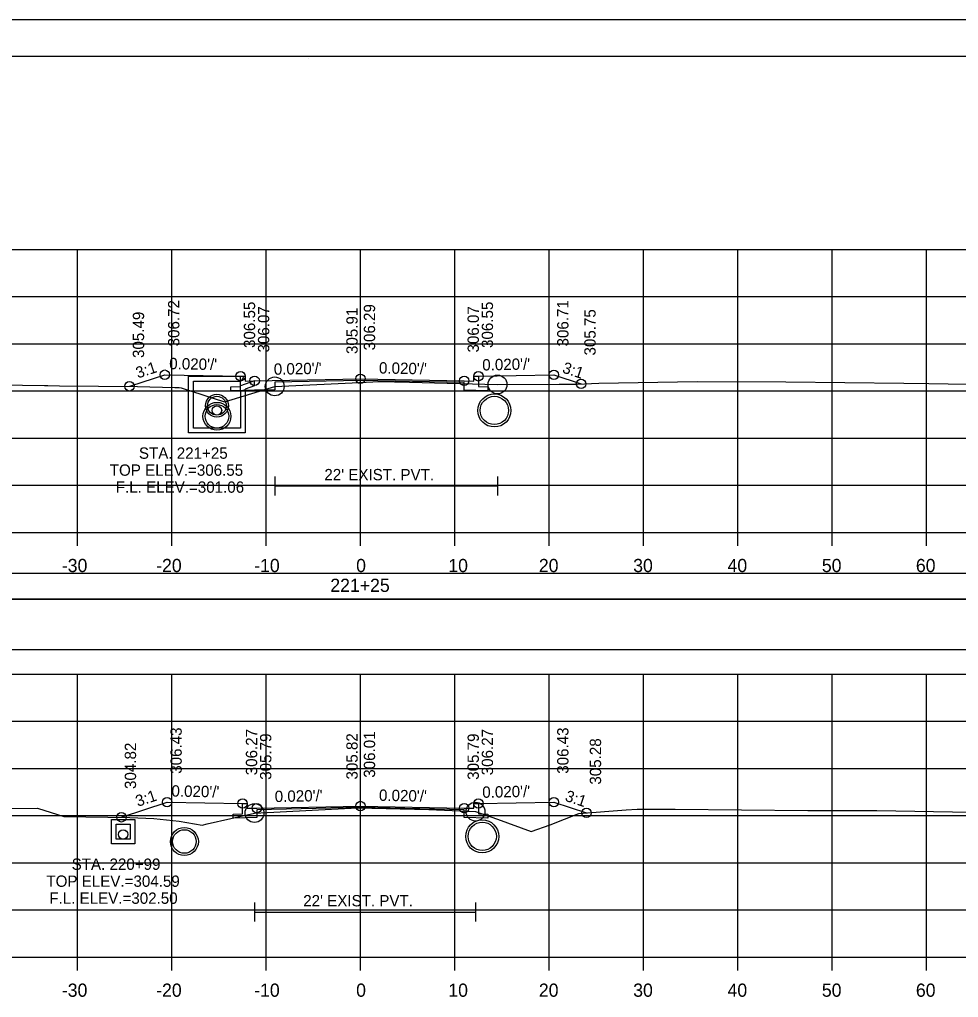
# Model space of a CAD drawing. Extents: x 1370538 to 1372872, y 376220 to 381127.
# Drawn here: x 1372672.5 to 1372772, y 379377.7 to 379481.3 of the extents above; entities that cross this region are included whole.
import ezdxf

# ---------------------------------------------------------------- set-up
doc = ezdxf.new("R2010")
doc.units = 0
for name, color, linetype in [('R_Border', 7, 'Continuous'), ('R_Border Notes', 7, 'Continuous'), ('R_Border PE', 7, 'Continuous'), ('R_Border Prem', 7, 'Continuous'), ('R_Dimension', 7, 'Continuous'), ('R_Fin Surface', 7, 'Continuous'), ('R_Grid', 7, 'Continuous'), ('R_No Plot', 7, 'Continuous'), ('R_Water', 7, 'Continuous'), ('R_Water Annot', 7, 'Continuous'), ('R_Xsect Elev', 7, 'Continuous'), ('R_Xsect Slope', 7, 'Continuous'), ('T_Detection Zones', 7, 'Continuous')]:
    doc.layers.add(name, color=color, linetype=linetype)

msp = doc.modelspace()

# ---------------------------------------------------------------- linework, layer by layer
at = {"layer": 'R_Border'}
for p, q in [((1372699.56, 379432.88), (1372699.56, 379430.88)), ((1372723.18, 379432.88), (1372723.18, 379430.88)), ((1372699.56, 379431.88), (1372723.18, 379431.88)), ((1372697.41, 379387.73), (1372697.41, 379385.73)), ((1372720.84, 379387.73), (1372720.84, 379385.73)), ((1372697.41, 379386.73), (1372720.84, 379386.73))]:
    msp.add_line(p, q, dxfattribs=at)
for points in [[(1372708.65, 379443.07), (1372699.56, 379442.89), (1372699.56, 379442.06), (1372697.43, 379442.02), (1372694.92, 379441.97), (1372694.92, 379442.39), (1372695.93, 379442.41), (1372695.93, 379443.5)], [(1372721.15, 379443.5), (1372721.15, 379442.41), (1372722.15, 379442.39), (1372722.15, 379441.97), (1372719.65, 379442.02), (1372719.65, 379442.02), (1372719.65, 379442.85), (1372708.65, 379443.07)], [(1372708.65, 379397.79), (1372697.65, 379397.57), (1372697.65, 379396.74), (1372697.65, 379396.74), (1372695.15, 379396.69), (1372695.15, 379397.11), (1372696.15, 379397.13), (1372696.15, 379398.22)], [(1372721.15, 379398.22), (1372721.15, 379397.13), (1372722.15, 379397.11), (1372722.15, 379396.69), (1372719.65, 379396.74), (1372719.65, 379396.74), (1372719.65, 379397.57), (1372708.65, 379397.79)]]:
    msp.add_lwpolyline(points, dxfattribs=at)
at = {"layer": 'R_Border Notes'}
for p, q in [((1372550.65, 379477.41), (1372866.83, 379477.41)), ((1372703.17, 379477.15), (1372703.17, 379477.15)), ((1372703.17, 379477.15), (1372703.17, 379477.15))]:
    msp.add_line(p, q, dxfattribs=at)
at = {"layer": 'R_Border Prem'}
for p, q in [((1372558.65, 379426.95), (1372858.65, 379426.95)), ((1372678.65, 379425.55), (1372678.65, 379426.95)), ((1372688.65, 379425.55), (1372688.65, 379426.95)), ((1372698.65, 379425.55), (1372698.65, 379426.95)), ((1372708.65, 379425.55), (1372708.65, 379426.95)), ((1372718.65, 379425.55), (1372718.65, 379426.95)), ((1372728.65, 379425.55), (1372728.65, 379426.95)), ((1372738.65, 379425.55), (1372738.65, 379426.95)), ((1372748.65, 379425.55), (1372748.65, 379426.95)), ((1372758.65, 379425.55), (1372758.65, 379426.95)), ((1372768.65, 379425.55), (1372768.65, 379426.95)), ((1372558.65, 379381.95), (1372858.65, 379381.95)), ((1372678.65, 379380.55), (1372678.65, 379381.95)), ((1372688.65, 379380.55), (1372688.65, 379381.95)), ((1372698.65, 379380.55), (1372698.65, 379381.95)), ((1372708.65, 379380.55), (1372708.65, 379381.95)), ((1372718.65, 379380.55), (1372718.65, 379381.95)), ((1372728.65, 379380.55), (1372728.65, 379381.95)), ((1372738.65, 379380.55), (1372738.65, 379381.95)), ((1372748.65, 379380.55), (1372748.65, 379381.95)), ((1372758.65, 379380.55), (1372758.65, 379381.95)), ((1372768.65, 379380.55), (1372768.65, 379381.95))]:
    msp.add_line(p, q, dxfattribs=at)
at = {"layer": 'R_Dimension'}
for points in [[(1372665.8, 379442.68), (1372675.15, 379442.53), (1372675.33, 379442.52), (1372675.52, 379442.52), (1372676.75, 379442.5), (1372685.01, 379442.43), (1372688.98, 379442.33), (1372689.43, 379442.32), (1372689.63, 379442.26), (1372694.24, 379440.79), (1372699.21, 379442.32), (1372699.56, 379442.43), (1372709.24, 379442.89), (1372710.67, 379442.95), (1372713.86, 379442.87), (1372723.18, 379442.63), (1372729.71, 379442.67), (1372731.63, 379442.68), (1372733.93, 379442.77), (1372744.36, 379442.96), (1372753.74, 379442.93), (1372766.25, 379442.76), (1372768.9, 379442.75), (1372775.04, 379442.64)], [(1372660.62, 379397.55), (1372674.4, 379397.75), (1372677.21, 379396.87), (1372684.21, 379396.75), (1372686.74, 379396.63), (1372689.41, 379396.36), (1372691.88, 379395.94), (1372692.4, 379396.09), (1372697.41, 379397.22), (1372703.53, 379397.54), (1372708.35, 379397.78), (1372715.89, 379397.58), (1372720.84, 379397.37), (1372723.18, 379396.57), (1372726.74, 379395.27), (1372728.75, 379395.98), (1372731.8, 379397.16), (1372736.83, 379397.56), (1372737.98, 379397.63), (1372742.02, 379397.62), (1372756.09, 379397.48), (1372763.38, 379397.5), (1372773.43, 379397.32)]]:
    msp.add_lwpolyline(points, dxfattribs=at)
at = {"layer": 'R_Fin Surface'}
for points in [[(1372684.16, 379442.44), (1372684.3, 379442.48), (1372687.9, 379443.67), (1372694.03, 379443.54), (1372695.93, 379443.5), (1372696.4, 379443.5), (1372696.43, 379443.5), (1372696.43, 379443.03), (1372696.43, 379443), (1372697.43, 379443.02), (1372708.65, 379443.24)], [(1372708.65, 379443.24), (1372719.65, 379443.02), (1372720.65, 379443), (1372720.65, 379443.5), (1372721.15, 379443.5), (1372729.15, 379443.66), (1372732.03, 379442.7)], [(1372683.31, 379396.77), (1372688.15, 379398.38), (1372696.15, 379398.22), (1372696.65, 379398.22), (1372696.65, 379397.72), (1372697.65, 379397.74), (1372708.65, 379397.96)], [(1372708.65, 379397.96), (1372719.65, 379397.74), (1372720.65, 379397.72), (1372720.65, 379398.22), (1372721.15, 379398.22), (1372729.15, 379398.38), (1372732.61, 379397.23)]]:
    msp.add_lwpolyline(points, dxfattribs=at)
at = {"layer": 'R_Grid'}
for p, q in [((1372558.65, 379456.95), (1372858.65, 379456.95)), ((1372678.65, 379426.95), (1372678.65, 379456.95)), ((1372688.65, 379426.95), (1372688.65, 379456.95)), ((1372698.65, 379426.95), (1372698.65, 379456.95)), ((1372708.65, 379426.95), (1372708.65, 379456.95)), ((1372718.65, 379426.95), (1372718.65, 379456.95)), ((1372728.65, 379426.95), (1372728.65, 379456.95)), ((1372738.65, 379426.95), (1372738.65, 379456.95)), ((1372748.65, 379426.95), (1372748.65, 379456.95)), ((1372758.65, 379426.95), (1372758.65, 379456.95)), ((1372768.65, 379426.95), (1372768.65, 379456.95)), ((1372558.65, 379451.95), (1372858.65, 379451.95)), ((1372558.65, 379446.95), (1372858.65, 379446.95)), ((1372558.65, 379441.95), (1372858.65, 379441.95)), ((1372558.65, 379436.95), (1372858.65, 379436.95)), ((1372558.65, 379431.95), (1372858.65, 379431.95)), ((1372558.65, 379426.95), (1372858.65, 379426.95)), ((1372558.65, 379411.95), (1372858.65, 379411.95)), ((1372678.65, 379381.95), (1372678.65, 379411.95)), ((1372688.65, 379381.95), (1372688.65, 379411.95)), ((1372698.65, 379381.95), (1372698.65, 379411.95)), ((1372708.65, 379381.95), (1372708.65, 379411.95)), ((1372718.65, 379381.95), (1372718.65, 379411.95)), ((1372728.65, 379381.95), (1372728.65, 379411.95)), ((1372738.65, 379381.95), (1372738.65, 379411.95)), ((1372748.65, 379381.95), (1372748.65, 379411.95)), ((1372758.65, 379381.95), (1372758.65, 379411.95)), ((1372768.65, 379381.95), (1372768.65, 379411.95)), ((1372558.65, 379406.95), (1372858.65, 379406.95)), ((1372558.65, 379401.95), (1372858.65, 379401.95)), ((1372558.65, 379396.95), (1372858.65, 379396.95)), ((1372558.65, 379391.95), (1372858.65, 379391.95)), ((1372558.65, 379386.95), (1372858.65, 379386.95)), ((1372558.65, 379381.95), (1372858.65, 379381.95))]:
    msp.add_line(p, q, dxfattribs=at)
at = {"layer": 'R_No Plot'}
msp.add_line((1372538.25, 379481.3), (1372871.58, 379481.3), dxfattribs=at)
for points in [[(1372538.24, 379481.3), (1372871.58, 379481.3), (1372871.58, 379267.96), (1372538.24, 379267.96)], [(1372784.57, 379477.41), (1372784.57, 379467.53), (1372820.3, 379467.53), (1372820.3, 379464.61), (1372843.5, 379464.61), (1372843.5, 379440.27), (1372866.83, 379440.27), (1372866.83, 379271.95), (1372550.65, 379271.95), (1372550.65, 379477.41)]]:
    msp.add_lwpolyline(points, close=True, dxfattribs=at)
for centre, radius in [((1372687.9, 379443.67), 0.5), ((1372695.93, 379443.5), 0.5), ((1372721.15, 379443.5), 0.5), ((1372729.15, 379443.66), 0.5), ((1372684.16, 379442.44), 0.5), ((1372697.43, 379443.02), 0.5), ((1372699.56, 379442.43), 1), ((1372708.65, 379443.24), 0.5), ((1372708.65, 379443.24), 0.5), ((1372719.65, 379443.02), 0.5), ((1372723.18, 379442.63), 1), ((1372732.03, 379442.7), 0.5), ((1372693.43, 379439.26), 1.48), ((1372693.43, 379440.38), 1.21), ((1372722.84, 379439.88), 1.75), ((1372693.43, 379439.88), 0.505), ((1372688.15, 379398.38), 0.5), ((1372696.15, 379398.22), 0.5), ((1372697.41, 379397.22), 1), ((1372697.65, 379397.74), 0.5), ((1372708.65, 379397.96), 0.5), ((1372708.65, 379397.96), 0.5), ((1372719.65, 379397.74), 0.5), ((1372720.84, 379397.37), 1), ((1372721.15, 379398.22), 0.5), ((1372729.15, 379398.38), 0.5), ((1372683.31, 379396.77), 0.5), ((1372732.61, 379397.23), 0.5), ((1372721.56, 379394.75), 1.75), ((1372683.49, 379394.95), 0.505), ((1372689.98, 379394.2), 1.48)]:
    msp.add_circle(centre, radius, dxfattribs=at)
at = {"layer": 'R_Water'}
for p, q in [((1372690.43, 379443.5), (1372696.18, 379443.5)), ((1372690.43, 379442), (1372690.43, 379443.5)), ((1372690.93, 379442), (1372690.93, 379443)), ((1372690.93, 379443), (1372695.93, 379443)), ((1372696.26, 379443.34), (1372695.93, 379443)), ((1372697.43, 379443.02), (1372695.93, 379442.5)), ((1372696.26, 379443.34), (1372696.18, 379443.5)), ((1372695.93, 379442), (1372695.93, 379442.5)), ((1372697.43, 379442.49), (1372696.43, 379442.15)), ((1372696.43, 379442), (1372696.43, 379442.15))]:
    msp.add_line(p, q, dxfattribs=at)
for points in [[(1372697.43, 379442.49), (1372697.43, 379443.02)], [(1372696.43, 379442), (1372696.43, 379437.51), (1372693.43, 379437.51), (1372690.43, 379437.51), (1372690.43, 379442)], [(1372695.93, 379442), (1372695.93, 379438.01), (1372693.43, 379438.01), (1372690.93, 379438.01), (1372690.93, 379442)]]:
    msp.add_lwpolyline(points, dxfattribs=at)
for points in [[(1372551.05, 379414.56), (1372866.18, 379414.56), (1372866.18, 379419.88), (1372551.05, 379419.88)], [(1372683.49, 379396.53), (1372684.74, 379396.53), (1372684.74, 379393.95), (1372683.49, 379393.95), (1372682.24, 379393.95), (1372682.24, 379396.53)], [(1372683.49, 379396.03), (1372684.24, 379396.03), (1372684.24, 379394.45), (1372683.49, 379394.45), (1372682.74, 379394.45), (1372682.74, 379396.03)]]:
    msp.add_lwpolyline(points, close=True, dxfattribs=at)
for centre, radius in [((1372693.43, 379440.38), 1), ((1372722.84, 379439.88), 1.5), ((1372693.43, 379439.26), 1.25), ((1372693.43, 379439.88), 0.5), ((1372721.56, 379394.75), 1.5), ((1372683.49, 379394.95), 0.5), ((1372689.98, 379394.2), 1.25)]:
    msp.add_circle(centre, radius, dxfattribs=at)
at = {"layer": 'R_Xsect Elev'}
for p, q in [((1372708.65, 379442.86), (1372708.65, 379452.86)), ((1372708.65, 379397.77), (1372708.65, 379407.77))]:
    msp.add_line(p, q, dxfattribs=at)
at = {"layer": 'T_Detection Zones'}
msp.add_lwpolyline([(1372551.05, 379419.88), (1372866.18, 379419.88), (1372866.18, 379422.59), (1372551.05, 379422.59)], close=True, dxfattribs=at)

# ---------------------------------------------------------------- texts
at = {"layer": 'R_Border PE'}
for s, p in [('-30', (1372676.99, 379422.75)), ('-20', (1372686.99, 379422.75)), ('-10', (1372697.38, 379422.75)), ('0', (1372708.19, 379422.75)), ('10', (1372717.96, 379422.75)), ('20', (1372727.56, 379422.75)), ('30', (1372737.56, 379422.75)), ('40', (1372747.56, 379422.75)), ('50', (1372757.56, 379422.75)), ('60', (1372767.53, 379422.75)), ('221+25', (1372705.45, 379420.65)), ('-30', (1372676.99, 379377.75)), ('-20', (1372686.99, 379377.75)), ('-10', (1372697.38, 379377.75)), ('0', (1372708.19, 379377.75)), ('10', (1372717.96, 379377.75)), ('20', (1372727.56, 379377.75)), ('30', (1372737.56, 379377.75)), ('40', (1372747.56, 379377.75)), ('50', (1372757.56, 379377.75)), ('60', (1372767.53, 379377.75))]:
    msp.add_text(s, height=1.4, dxfattribs=at).set_placement(p)
at = {"layer": 'R_Water'}
for p in [(1372704.82, 379432.48), (1372702.58, 379387.33)]:
    msp.add_text("22' EXIST. PVT.", height=1.2, dxfattribs=at).set_placement(p)
at = {"layer": 'R_Water Annot'}
for s, p in [('STA. 221+25', (1372685.16, 379434.76)), ('TOP ELEV.=306.55', (1372682.07, 379432.96)), ('F.L. ELEV.=301.06', (1372682.71, 379431.16)), ('STA. 220+99', (1372678.03, 379391.2)), ('TOP ELEV.=304.59', (1372675.35, 379389.4)), ('F.L. ELEV.=302.50', (1372675.66, 379387.6))]:
    msp.add_text(s, height=1.2, dxfattribs=at).set_placement(p)
at = {"layer": 'R_Xsect Elev'}
for s, p in [('306.72', (1372689.45, 379446.67)), ('306.55', (1372697.48, 379446.5)), ('306.29', (1372710.2, 379446.24)), ('306.29', (1372710.2, 379446.24)), ('306.55', (1372722.7, 379446.5)), ('306.71', (1372730.7, 379446.66)), ('305.49', (1372685.71, 379445.44)), ('306.07', (1372698.98, 379446.02)), ('305.91', (1372708.35, 379445.86)), ('306.07', (1372721.2, 379446.02)), ('305.75', (1372733.58, 379445.7)), ('306.43', (1372689.7, 379401.38)), ('306.27', (1372697.7, 379401.22)), ('305.79', (1372699.2, 379400.74)), ('305.82', (1372708.35, 379400.77)), ('306.01', (1372710.2, 379400.96)), ('305.79', (1372721.2, 379400.74)), ('306.27', (1372722.7, 379401.22)), ('306.43', (1372730.7, 379401.38)), ('304.82', (1372684.86, 379399.77)), ('305.28', (1372734.16, 379400.23))]:
    msp.add_text(s, height=1.2, rotation=90, dxfattribs=at).set_placement(p)
at = {"layer": 'R_Xsect Slope'}
for s, rotation, p in [('3:1', 18.2816, (1372685.05, 379443.26)), ("0.020'/'", 358.7855, (1372688.36, 379444.26)), ("0.020'/'", 1.1192, (1372699.47, 379443.66)), ("0.020'/'", 358.8542, (1372710.6, 379443.8)), ("0.020'/'", 1.1458, (1372721.57, 379444.11)), ('3:1', 341.5651, (1372729.96, 379443.92)), ('3:1', 18.4349, (1372685.04, 379397.87)), ("0.020'/'", 358.8542, (1372688.6, 379398.97)), ("0.020'/'", 1.1458, (1372699.57, 379398.38)), ("0.020'/'", 358.8542, (1372710.6, 379398.52)), ("0.020'/'", 1.1458, (1372721.57, 379398.83)), ('3:1', 341.5651, (1372730.25, 379398.54))]:
    msp.add_text(s, height=1.2, rotation=rotation, dxfattribs=at).set_placement(p)

doc.saveas('drawing.dxf')
